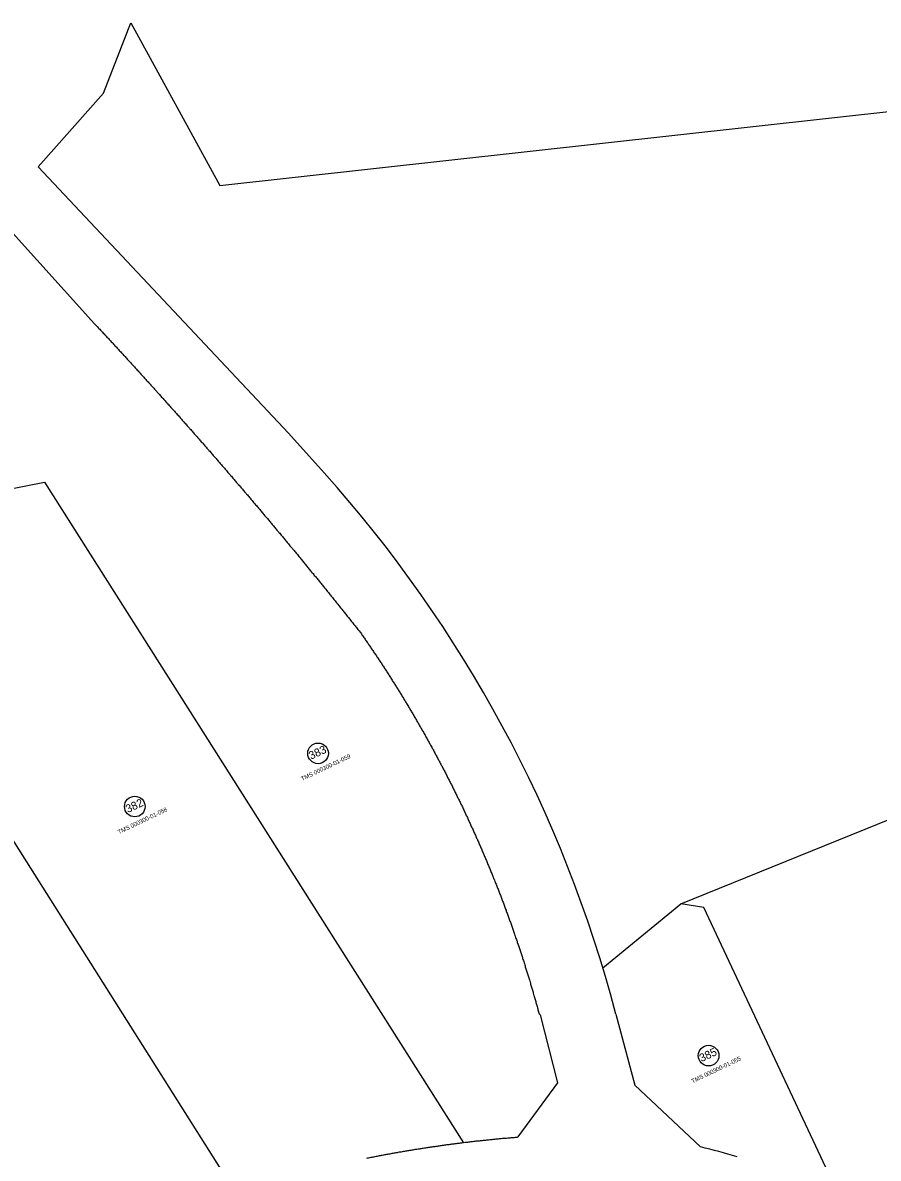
# Model space of a CAD drawing. Extents: x 1854757 to 1948870, y 823643 to 877716.
# Drawn here: x 1903282 to 1904083, y 853837 to 854901 of the extents above; entities that cross this region are included whole.
import ezdxf

# ---------------------------------------------------------------- set-up
doc = ezdxf.new("R2010")
doc.units = 0
for name, color, linetype in [('Butler baseline', 7, 'Continuous'), ('Flatiron trailer_2', 7, 'Continuous'), ('RD_EX_H2O_WetLd', 7, 'Continuous'), ('RD_SMD_Misc', 7, 'Continuous')]:
    doc.layers.add(name, color=color, linetype=linetype)

msp = doc.modelspace()

# ---------------------------------------------------------------- linework, layer by layer
at = {"layer": 'Butler baseline'}
for centre in [(1903558.5, 854216.2), (1903386.8, 854166.4), (1903924.4, 853933)]:
    msp.add_circle(centre, 9.65, dxfattribs=at)
at = {"layer": 'RD_EX_H2O_WetLd'}
for p, q in [((1903357.4, 854834.7), (1903383.1, 854900.8)), ((1903383.1, 854900.8), (1903466.5, 854748.3)), ((1903466.5, 854748.3), (1904319.8, 854842.7)), ((1903296.4, 854765.7), (1903357.4, 854834.7)), ((1903530.7, 854516.1), (1903296.4, 854765.7)), ((1903898.5, 854075.1), (1904882, 854475.2)), ((1903825.3, 854015.4), (1903898.5, 854075.1)), ((1903919.8, 854071.8), (1903898.5, 854075.1)), ((1904046.6, 853801.8), (1903919.8, 854071.8))]:
    msp.add_line(p, q, dxfattribs=at)
for points in [[(1903266.6, 854710.2), (1903349.1, 854618.7), (1903349.8, 854618), (1903350.5, 854617.2), (1903351.2, 854616.5), (1903351.9, 854615.8), (1903352.5, 854615), (1903353.2, 854614.3), (1903353.9, 854613.6), (1903354.6, 854612.8), (1903355.3, 854612.1), (1903356, 854611.4), (1903356.6, 854610.7), (1903357.3, 854609.9), (1903358, 854609.2), (1903358.7, 854608.5), (1903359.4, 854607.7), (1903360, 854607), (1903360.7, 854606.3), (1903361.4, 854605.5), (1903362.1, 854604.8), (1903362.8, 854604.1), (1903363.4, 854603.3), (1903364.1, 854602.6), (1903364.8, 854601.9), (1903365.5, 854601.1), (1903366.2, 854600.4), (1903366.8, 854599.6), (1903367.5, 854598.9), (1903368.2, 854598.2), (1903368.9, 854597.4), (1903369.5, 854596.7), (1903370.2, 854596), (1903370.9, 854595.2), (1903371.6, 854594.5), (1903372.3, 854593.8), (1903372.9, 854593), (1903373.6, 854592.3), (1903374.3, 854591.6), (1903375, 854590.8), (1903375.6, 854590.1), (1903376.3, 854589.3), (1903377, 854588.6), (1903377.7, 854587.9), (1903378.3, 854587.1), (1903379, 854586.4), (1903379.7, 854585.7), (1903380.4, 854584.9), (1903381, 854584.2), (1903381.7, 854583.5), (1903382.4, 854582.7), (1903383.1, 854582), (1903383.7, 854581.2), (1903384.4, 854580.5), (1903385.1, 854579.8), (1903385.8, 854579), (1903386.4, 854578.3), (1903387.1, 854577.5), (1903387.8, 854576.8), (1903388.5, 854576.1), (1903389.1, 854575.3), (1903389.8, 854574.6), (1903390.5, 854573.8), (1903391.2, 854573.1), (1903391.8, 854572.4), (1903392.5, 854571.6), (1903393.2, 854570.9), (1903393.8, 854570.1), (1903394.5, 854569.4), (1903395.2, 854568.7), (1903395.9, 854567.9), (1903396.5, 854567.2), (1903397.2, 854566.4), (1903397.9, 854565.7), (1903398.5, 854565), (1903399.2, 854564.2), (1903399.9, 854563.5), (1903400.6, 854562.7), (1903401.2, 854562), (1903401.9, 854561.3), (1903402.6, 854560.5), (1903403.2, 854559.8), (1903403.9, 854559), (1903404.6, 854558.3), (1903405.3, 854557.5), (1903405.9, 854556.8), (1903406.6, 854556.1), (1903407.3, 854555.3), (1903407.9, 854554.6), (1903408.6, 854553.8), (1903409.3, 854553.1), (1903409.9, 854552.3), (1903410.6, 854551.6), (1903411.3, 854550.9), (1903411.9, 854550.1), (1903412.6, 854549.4), (1903413.3, 854548.6), (1903413.9, 854547.9), (1903414.6, 854547.1), (1903415.3, 854546.4), (1903415.9, 854545.6), (1903416.6, 854544.9), (1903417.3, 854544.2), (1903417.9, 854543.4), (1903418.6, 854542.7), (1903419.3, 854541.9), (1903419.9, 854541.2), (1903420.6, 854540.4), (1903421.3, 854539.7), (1903421.9, 854538.9), (1903422.6, 854538.2), (1903423.3, 854537.4), (1903423.9, 854536.7), (1903424.6, 854535.9), (1903425.3, 854535.2), (1903425.9, 854534.5), (1903426.6, 854533.7), (1903427.3, 854533), (1903427.9, 854532.2), (1903428.6, 854531.5), (1903429.3, 854530.7), (1903429.9, 854530), (1903430.6, 854529.2), (1903431.2, 854528.5), (1903431.9, 854527.7), (1903432.6, 854527), (1903433.2, 854526.2), (1903433.9, 854525.5), (1903434.6, 854524.7), (1903435.2, 854524), (1903435.9, 854523.2), (1903436.5, 854522.5), (1903437.2, 854521.7), (1903437.9, 854521), (1903438.5, 854520.2), (1903439.2, 854519.5), (1903439.9, 854518.7), (1903440.5, 854518), (1903441.2, 854517.2), (1903441.8, 854516.5), (1903442.5, 854515.7), (1903443.2, 854515), (1903443.8, 854514.2), (1903444.5, 854513.5), (1903445.1, 854512.7), (1903445.8, 854512), (1903446.5, 854511.2), (1903447.1, 854510.5), (1903447.8, 854509.7), (1903448.4, 854509), (1903449.1, 854508.2), (1903449.8, 854507.5), (1903450.4, 854506.7), (1903451.1, 854506), (1903451.7, 854505.2), (1903452.4, 854504.5), (1903453.1, 854503.7), (1903453.7, 854503), (1903454.4, 854502.2), (1903455, 854501.4), (1903455.7, 854500.7), (1903456.3, 854499.9), (1903457, 854499.2), (1903457.7, 854498.4), (1903458.3, 854497.7), (1903459, 854496.9), (1903459.6, 854496.2), (1903460.3, 854495.4), (1903460.9, 854494.7), (1903461.6, 854493.9), (1903462.3, 854493.1), (1903462.9, 854492.4), (1903463.6, 854491.6), (1903464.2, 854490.9), (1903464.9, 854490.1), (1903465.5, 854489.4), (1903466.2, 854488.6), (1903466.8, 854487.9), (1903467.5, 854487.1), (1903468.1, 854486.4), (1903468.8, 854485.6), (1903469.5, 854484.8), (1903470.1, 854484.1), (1903470.8, 854483.3), (1903471.4, 854482.6), (1903472.1, 854481.8), (1903472.7, 854481.1), (1903473.4, 854480.3), (1903474, 854479.5), (1903474.7, 854478.8), (1903475.3, 854478), (1903476, 854477.3), (1903476.6, 854476.5), (1903477.3, 854475.8), (1903478, 854475), (1903478.6, 854474.2), (1903479.3, 854473.5), (1903479.9, 854472.7), (1903480.6, 854472), (1903481.2, 854471.2), (1903481.9, 854470.4), (1903482.5, 854469.7), (1903483.2, 854468.9), (1903483.8, 854468.2), (1903484.5, 854467.4), (1903485.1, 854466.6), (1903485.8, 854465.9), (1903486.4, 854465.1), (1903487.1, 854464.4), (1903487.7, 854463.6), (1903488.4, 854462.8), (1903489, 854462.1), (1903489.7, 854461.3), (1903490.3, 854460.6), (1903491, 854459.8), (1903491.6, 854459), (1903492.3, 854458.3), (1903492.9, 854457.5), (1903493.6, 854456.8), (1903494.2, 854456), (1903494.9, 854455.2), (1903495.5, 854454.5), (1903496.1, 854453.7), (1903496.8, 854453), (1903497.4, 854452.2), (1903498.1, 854451.4), (1903498.7, 854450.7), (1903499.4, 854449.9), (1903500, 854449.1), (1903500.7, 854448.4), (1903501.3, 854447.6), (1903502, 854446.9), (1903502.6, 854446.1), (1903503.3, 854445.3), (1903503.9, 854444.6), (1903504.6, 854443.8), (1903505.2, 854443), (1903505.8, 854442.3), (1903506.5, 854441.5), (1903507.1, 854440.7), (1903507.8, 854440), (1903508.4, 854439.2), (1903509.1, 854438.4), (1903509.7, 854437.7), (1903510.4, 854436.9), (1903511, 854436.2), (1903511.6, 854435.4), (1903512.3, 854434.6), (1903512.9, 854433.9), (1903513.6, 854433.1), (1903514.2, 854432.3), (1903514.9, 854431.6), (1903515.5, 854430.8), (1903516.1, 854430), (1903516.8, 854429.3), (1903517.4, 854428.5), (1903518.1, 854427.7), (1903518.7, 854427), (1903519.4, 854426.2), (1903520, 854425.4), (1903520.6, 854424.7), (1903521.3, 854423.9), (1903521.9, 854423.1), (1903522.6, 854422.4), (1903523.2, 854421.6), (1903523.8, 854420.8), (1903524.5, 854420.1), (1903525.1, 854419.3), (1903525.8, 854418.5), (1903526.4, 854417.8), (1903527, 854417), (1903527.7, 854416.2), (1903528.3, 854415.4), (1903529, 854414.7), (1903529.6, 854413.9), (1903530.2, 854413.1), (1903530.9, 854412.4), (1903531.5, 854411.6), (1903532.2, 854410.8), (1903532.8, 854410.1), (1903533.4, 854409.3), (1903534.1, 854408.5), (1903534.7, 854407.8), (1903535.4, 854407), (1903536, 854406.2), (1903536.6, 854405.4), (1903537.3, 854404.7), (1903537.9, 854403.9), (1903538.5, 854403.1), (1903539.2, 854402.4), (1903539.8, 854401.6), (1903540.5, 854400.8), (1903541.1, 854400), (1903541.7, 854399.3), (1903542.4, 854398.5), (1903543, 854397.7), (1903543.6, 854397), (1903544.3, 854396.2), (1903544.9, 854395.4), (1903545.5, 854394.6), (1903546.2, 854393.9), (1903546.8, 854393.1), (1903547.4, 854392.3), (1903548.1, 854391.6), (1903548.7, 854390.8), (1903549.3, 854390), (1903550, 854389.2), (1903550.6, 854388.5), (1903551.2, 854387.7), (1903551.9, 854386.9), (1903552.5, 854386.1), (1903553.1, 854385.4), (1903553.8, 854384.6), (1903554.4, 854383.8), (1903555, 854383), (1903555.7, 854382.3), (1903556.3, 854381.5), (1903556.9, 854380.7), (1903557.6, 854379.9), (1903558.2, 854379.2), (1903558.8, 854378.4), (1903559.5, 854377.6), (1903560.1, 854376.8), (1903560.7, 854376.1), (1903561.4, 854375.3), (1903562, 854374.5), (1903562.6, 854373.7), (1903563.3, 854373), (1903563.9, 854372.2), (1903564.5, 854371.4), (1903565.1, 854370.6), (1903565.8, 854369.9), (1903566.4, 854369.1), (1903567, 854368.3), (1903567.7, 854367.5), (1903568.3, 854366.8), (1903568.9, 854366), (1903569.6, 854365.2), (1903570.2, 854364.4), (1903570.8, 854363.6), (1903571.4, 854362.9), (1903572.1, 854362.1), (1903572.7, 854361.3), (1903573.3, 854360.5), (1903574, 854359.8), (1903574.6, 854359), (1903575.2, 854358.2), (1903575.8, 854357.4), (1903576.5, 854356.6), (1903577.1, 854355.9), (1903577.7, 854355.1), (1903578.3, 854354.3), (1903579, 854353.5), (1903579.6, 854352.7), (1903580.2, 854352), (1903580.9, 854351.2), (1903581.5, 854350.4), (1903582.1, 854349.6), (1903582.7, 854348.8), (1903583.4, 854348.1), (1903584, 854347.3), (1903584.6, 854346.5), (1903585.2, 854345.7), (1903585.9, 854344.9), (1903586.5, 854344.2), (1903587.1, 854343.4), (1903587.7, 854342.6), (1903588.4, 854341.8), (1903589, 854341), (1903589.6, 854340.2), (1903590.2, 854339.5), (1903590.8, 854338.7), (1903591.5, 854337.9), (1903592.1, 854337.1), (1903592.7, 854336.3), (1903593.3, 854335.6), (1903594, 854334.8), (1903594.6, 854334), (1903595.2, 854333.2), (1903595.8, 854332.4), (1903596.4, 854331.6), (1903597.1, 854330.9), (1903597.9, 854329.8), (1903598.5, 854329), (1903599.1, 854328.2), (1903599.6, 854327.3), (1903600.2, 854326.5), (1903600.8, 854325.7), (1903601.3, 854324.9), (1903601.9, 854324.1), (1903602.5, 854323.2), (1903603.1, 854322.4), (1903603.6, 854321.6), (1903604.2, 854320.8), (1903604.8, 854319.9), (1903605.3, 854319.1), (1903605.9, 854318.3), (1903606.4, 854317.5), (1903607, 854316.6), (1903607.6, 854315.8), (1903608.1, 854315), (1903608.7, 854314.2), (1903609.3, 854313.3), (1903609.8, 854312.5), (1903610.4, 854311.7), (1903610.9, 854310.8), (1903611.5, 854310), (1903612.1, 854309.2), (1903612.6, 854308.4), (1903613.2, 854307.5), (1903613.7, 854306.7), (1903614.3, 854305.9), (1903614.8, 854305), (1903615.4, 854304.2), (1903615.9, 854303.4), (1903616.5, 854302.5), (1903617, 854301.7), (1903617.6, 854300.9), (1903618.1, 854300), (1903618.7, 854299.2), (1903619.2, 854298.3), (1903619.8, 854297.5), (1903620.3, 854296.7), (1903620.9, 854295.8), (1903621.4, 854295), (1903621.9, 854294.1), (1903622.5, 854293.3), (1903623, 854292.5), (1903623.6, 854291.6), (1903624.1, 854290.8), (1903624.7, 854289.9), (1903625.2, 854289.1), (1903625.7, 854288.3), (1903626.3, 854287.4), (1903626.8, 854286.6), (1903627.3, 854285.7), (1903627.9, 854284.9), (1903628.4, 854284), (1903629, 854283.2), (1903629.5, 854282.4), (1903630, 854281.5), (1903630.5, 854280.7), (1903631.1, 854279.8), (1903631.6, 854279), (1903632.1, 854278.1), (1903632.7, 854277.3), (1903633.2, 854276.4), (1903633.7, 854275.6), (1903634.3, 854274.7), (1903634.8, 854273.9), (1903635.3, 854273), (1903635.8, 854272.2), (1903636.3, 854271.3), (1903636.9, 854270.5), (1903637.4, 854269.6), (1903637.9, 854268.8), (1903638.4, 854267.9), (1903639, 854267), (1903639.5, 854266.2), (1903640, 854265.3), (1903640.5, 854264.5), (1903641, 854263.6), (1903641.5, 854262.8), (1903642.1, 854261.9), (1903642.6, 854261.1), (1903643.1, 854260.2), (1903643.6, 854259.3), (1903644.1, 854258.5), (1903644.6, 854257.6), (1903645.1, 854256.8), (1903645.6, 854255.9), (1903646.2, 854255), (1903646.7, 854254.2), (1903647.2, 854253.3), (1903647.7, 854252.5), (1903648.2, 854251.6), (1903648.7, 854250.7), (1903649.2, 854249.9), (1903649.7, 854249), (1903650.2, 854248.1), (1903650.7, 854247.3), (1903651.2, 854246.4), (1903651.7, 854245.5), (1903652.2, 854244.7), (1903652.7, 854243.8), (1903653.2, 854242.9), (1903653.7, 854242.1), (1903654.2, 854241.2), (1903654.7, 854240.3), (1903655.2, 854239.5), (1903655.7, 854238.6), (1903656.2, 854237.7), (1903656.7, 854236.9), (1903657.2, 854236), (1903657.7, 854235.1), (1903658.2, 854234.3), (1903658.7, 854233.4), (1903659.1, 854232.5), (1903659.6, 854231.6), (1903660.1, 854230.8), (1903660.6, 854229.9), (1903661.1, 854229), (1903661.6, 854228.1), (1903662.1, 854227.3), (1903662.5, 854226.4), (1903663, 854225.5), (1903663.5, 854224.7), (1903664, 854223.8), (1903664.5, 854222.9), (1903665, 854222), (1903665.4, 854221.1), (1903665.9, 854220.3), (1903666.4, 854219.4), (1903666.9, 854218.5), (1903667.4, 854217.6), (1903667.8, 854216.7), (1903668.3, 854215.9), (1903668.8, 854215), (1903669.3, 854214.1), (1903669.7, 854213.2), (1903670.2, 854212.3), (1903670.7, 854211.5), (1903671.1, 854210.6), (1903671.6, 854209.7), (1903672.1, 854208.8), (1903672.5, 854207.9), (1903673, 854207), (1903673.5, 854206.2), (1903673.9, 854205.3), (1903674.4, 854204.4), (1903674.9, 854203.5), (1903675.3, 854202.6), (1903675.8, 854201.7), (1903676.3, 854200.8), (1903676.7, 854200), (1903677.2, 854199.1), (1903677.6, 854198.2), (1903678.1, 854197.3), (1903678.6, 854196.4), (1903679, 854195.5), (1903679.5, 854194.6), (1903679.9, 854193.7), (1903680.4, 854192.8), (1903680.8, 854192), (1903681.3, 854191.1), (1903681.8, 854190.2), (1903682.2, 854189.3), (1903682.7, 854188.4), (1903683.1, 854187.5), (1903683.6, 854186.6), (1903684, 854185.7), (1903684.5, 854184.8), (1903684.9, 854183.9), (1903685.3, 854183), (1903685.8, 854182.1), (1903686.2, 854181.2), (1903686.7, 854180.3), (1903687.1, 854179.4), (1903687.6, 854178.5), (1903688, 854177.7), (1903688.5, 854176.8), (1903688.9, 854175.9), (1903689.3, 854175), (1903689.8, 854174.1), (1903690.2, 854173.2), (1903690.6, 854172.3), (1903691.1, 854171.4), (1903691.5, 854170.5), (1903691.9, 854169.6), (1903692.4, 854168.7), (1903692.8, 854167.8), (1903693.2, 854166.9), (1903693.7, 854166), (1903694.1, 854165.1), (1903694.5, 854164.2), (1903695, 854163.2), (1903695.4, 854162.3), (1903695.8, 854161.4), (1903696.3, 854160.5), (1903696.7, 854159.6), (1903697.1, 854158.7), (1903697.5, 854157.8), (1903698, 854156.9), (1903698.4, 854156), (1903698.8, 854155.1), (1903699.2, 854154.2), (1903699.6, 854153.3), (1903700.1, 854152.4), (1903700.5, 854151.5), (1903700.9, 854150.6), (1903701.3, 854149.7), (1903701.7, 854148.7), (1903702.1, 854147.8), (1903702.6, 854146.9), (1903703, 854146), (1903703.4, 854145.1), (1903703.8, 854144.2), (1903704.2, 854143.3), (1903704.6, 854142.4), (1903705, 854141.5), (1903705.4, 854140.5), (1903705.9, 854139.6), (1903706.3, 854138.7), (1903706.7, 854137.8), (1903707.1, 854136.9), (1903707.5, 854136), (1903707.9, 854135.1), (1903708.3, 854134.2), (1903708.7, 854133.2), (1903709.1, 854132.3), (1903709.5, 854131.4), (1903709.9, 854130.5), (1903710.3, 854129.6), (1903710.7, 854128.7), (1903711.1, 854127.7), (1903711.5, 854126.8), (1903711.9, 854125.9), (1903712.3, 854125), (1903712.7, 854124.1), (1903713.1, 854123.1), (1903713.5, 854122.2), (1903713.9, 854121.3), (1903714.2, 854120.4), (1903714.6, 854119.5), (1903715, 854118.5), (1903715.4, 854117.6), (1903715.8, 854116.7), (1903716.2, 854115.8), (1903716.6, 854114.9), (1903717, 854113.9), (1903717.4, 854113), (1903717.7, 854112.1), (1903718.1, 854111.2), (1903718.5, 854110.2), (1903718.9, 854109.3), (1903719.3, 854108.4), (1903719.7, 854107.5), (1903720, 854106.5), (1903720.4, 854105.6), (1903720.8, 854104.7), (1903721.2, 854103.8), (1903721.5, 854102.8), (1903721.9, 854101.9), (1903722.3, 854101), (1903722.7, 854100.1), (1903723, 854099.1), (1903723.4, 854098.2), (1903723.8, 854097.3), (1903724.2, 854096.3), (1903724.5, 854095.4), (1903724.9, 854094.5), (1903725.3, 854093.6), (1903725.6, 854092.6), (1903726, 854091.7), (1903726.4, 854090.8), (1903726.7, 854089.8), (1903727.1, 854088.9), (1903727.5, 854088), (1903727.8, 854087), (1903728.2, 854086.1), (1903728.5, 854085.2), (1903728.9, 854084.2), (1903729.3, 854083.3), (1903729.6, 854082.4), (1903730, 854081.4), (1903730.3, 854080.5), (1903730.7, 854079.6), (1903731, 854078.6), (1903731.4, 854077.7), (1903731.8, 854076.8), (1903732.1, 854075.8), (1903732.5, 854074.9), (1903732.8, 854074), (1903733.2, 854073), (1903733.5, 854072.1), (1903733.9, 854071.1), (1903734.2, 854070.2), (1903734.6, 854069.3), (1903734.9, 854068.3), (1903735.2, 854067.4), (1903735.6, 854066.5), (1903735.9, 854065.5), (1903736.3, 854064.6), (1903736.6, 854063.6), (1903737, 854062.7), (1903737.3, 854061.8), (1903737.6, 854060.8), (1903738, 854059.9), (1903738.3, 854058.9), (1903738.7, 854058), (1903739, 854057.1), (1903739.3, 854056.1), (1903739.7, 854055.2), (1903740, 854054.2), (1903740.3, 854053.3), (1903740.7, 854052.3), (1903741, 854051.4), (1903741.3, 854050.5), (1903741.6, 854049.5), (1903742, 854048.6), (1903742.3, 854047.6), (1903742.6, 854046.7), (1903743, 854045.7), (1903743.3, 854044.8), (1903743.6, 854043.8), (1903743.9, 854042.9), (1903744.3, 854041.9), (1903744.6, 854041), (1903744.9, 854040.1), (1903745.2, 854039.1), (1903745.5, 854038.2), (1903745.9, 854037.2), (1903746.2, 854036.3), (1903746.5, 854035.3), (1903746.8, 854034.4), (1903747.1, 854033.4), (1903747.4, 854032.5), (1903747.8, 854031.5), (1903748.1, 854030.6), (1903748.4, 854029.6), (1903748.7, 854028.7), (1903749, 854027.7), (1903749.3, 854026.8), (1903749.6, 854025.8), (1903749.9, 854024.9), (1903750.2, 854023.9), (1903750.5, 854023), (1903750.9, 854022), (1903751.2, 854021.1), (1903751.5, 854020.1), (1903751.8, 854019.2), (1903752.1, 854018.2), (1903752.4, 854017.2), (1903752.7, 854016.3), (1903753, 854015.3), (1903753.3, 854014.4), (1903753.6, 854013.4), (1903753.9, 854012.5), (1903754.2, 854011.5), (1903754.5, 854010.6), (1903754.8, 854009.6), (1903755, 854008.7), (1903755.3, 854007.7), (1903755.6, 854006.7), (1903755.9, 854005.8), (1903756.2, 854004.8), (1903756.5, 854003.9), (1903756.8, 854002.9), (1903757.1, 854002), (1903757.4, 854001), (1903757.7, 854000), (1903757.9, 853999.1), (1903758.2, 853998.1), (1903758.5, 853997.2), (1903758.8, 853996.2), (1903759.1, 853995.2), (1903759.4, 853994.3), (1903759.6, 853993.3), (1903759.9, 853992.4), (1903760.2, 853991.4), (1903760.5, 853990.4), (1903760.8, 853989.5), (1903761, 853988.5), (1903761.3, 853987.6), (1903761.6, 853986.6), (1903761.9, 853985.6), (1903762.1, 853984.7), (1903762.4, 853983.7), (1903762.7, 853982.8), (1903762.9, 853981.8), (1903763.2, 853980.8), (1903763.5, 853979.9), (1903763.7, 853978.9), (1903764, 853977.9), (1903764.3, 853977), (1903764.5, 853976), (1903764.8, 853975), (1903765.1, 853974.1), (1903765.3, 853973.1), (1903765.6, 853972.2), (1903766.6, 853971.3), (1903783, 853907.5), (1903745.6, 853856.9), (1903745.2, 853856.3), (1903744.2, 853856.3), (1903743.2, 853856.2), (1903742.2, 853856.1), (1903741.2, 853856), (1903740.2, 853855.9), (1903739.2, 853855.9), (1903738.2, 853855.8), (1903737.2, 853855.7), (1903736.2, 853855.6), (1903735.2, 853855.5), (1903734.2, 853855.4), (1903733.2, 853855.4), (1903732.2, 853855.3), (1903731.2, 853855.2), (1903730.2, 853855.1), (1903729.2, 853855), (1903728.2, 853854.9), (1903727.2, 853854.8), (1903726.2, 853854.7), (1903725.2, 853854.6), (1903724.2, 853854.5), (1903723.2, 853854.4), (1903722.2, 853854.3), (1903721.2, 853854.2), (1903720.3, 853854.1), (1903719.3, 853854), (1903718.3, 853853.9), (1903717.3, 853853.8), (1903716.3, 853853.7), (1903715.3, 853853.6), (1903714.3, 853853.5), (1903713.3, 853853.4), (1903712.3, 853853.3), (1903711.3, 853853.2), (1903710.3, 853853.1), (1903709.3, 853853), (1903708.3, 853852.9), (1903707.3, 853852.8), (1903706.3, 853852.7), (1903705.3, 853852.6), (1903704.3, 853852.4), (1903703.3, 853852.3), (1903702.4, 853852.2), (1903701.4, 853852.1), (1903700.4, 853852), (1903699.4, 853851.9), (1903698.4, 853851.7), (1903697.4, 853851.6), (1903696.4, 853851.5), (1903694.8, 853851.3)], [(1903494.1, 853784.8), (1902909.8, 854708.8)], [(1903171.5, 854444.6), (1903302.2, 854470.2), (1903694.8, 853851.3), (1903693.8, 853851.2), (1903692.8, 853851.1), (1903691.8, 853850.9), (1903690.8, 853850.8), (1903689.8, 853850.7), (1903688.8, 853850.6), (1903687.8, 853850.4), (1903686.8, 853850.3), (1903685.8, 853850.2), (1903684.8, 853850.1), (1903683.8, 853849.9), (1903682.9, 853849.8), (1903681.9, 853849.7), (1903680.9, 853849.5), (1903679.9, 853849.4), (1903678.9, 853849.3), (1903677.9, 853849.1), (1903676.9, 853849), (1903675.9, 853848.9), (1903674.9, 853848.7), (1903673.9, 853848.6), (1903672.9, 853848.5), (1903672, 853848.3), (1903671, 853848.2), (1903670, 853848), (1903669, 853847.9), (1903668, 853847.7), (1903667, 853847.6), (1903666, 853847.5), (1903665, 853847.3), (1903664, 853847.2), (1903663.1, 853847), (1903662.1, 853846.9), (1903661.1, 853846.7), (1903660.1, 853846.6), (1903659.1, 853846.4), (1903658.1, 853846.3), (1903657.1, 853846.1), (1903656.1, 853846), (1903655.1, 853845.8), (1903654.2, 853845.7), (1903653.2, 853845.5), (1903652.2, 853845.3), (1903651.2, 853845.2), (1903650.2, 853845), (1903649.2, 853844.9), (1903648.2, 853844.7), (1903647.2, 853844.5), (1903646.3, 853844.4), (1903645.3, 853844.2), (1903644.3, 853844.1), (1903643.3, 853843.9), (1903642.3, 853843.7), (1903641.3, 853843.6), (1903640.3, 853843.4), (1903639.4, 853843.2), (1903638.4, 853843.1), (1903637.4, 853842.9), (1903636.4, 853842.7), (1903635.4, 853842.6), (1903634.4, 853842.4), (1903633.4, 853842.2), (1903632.5, 853842), (1903631.5, 853841.9), (1903630.5, 853841.7), (1903629.5, 853841.5), (1903628.5, 853841.3), (1903627.5, 853841.2), (1903626.6, 853841), (1903625.6, 853840.8), (1903624.6, 853840.6), (1903623.6, 853840.4), (1903622.6, 853840.3), (1903621.6, 853840.1), (1903620.7, 853839.9), (1903619.7, 853839.7), (1903618.7, 853839.5), (1903617.7, 853839.3), (1903616.7, 853839.2), (1903615.7, 853839), (1903614.8, 853838.8), (1903613.8, 853838.6), (1903612.8, 853838.4), (1903611.8, 853838.2), (1903610.8, 853838), (1903609.8, 853837.8), (1903608.9, 853837.6), (1903607.9, 853837.4), (1903606.9, 853837.2), (1903605.9, 853837), (1903604.9, 853836.9), (1903604, 853836.7)]]:
    msp.add_lwpolyline(points, dxfattribs=at)
at = {"layer": 'RD_SMD_Misc'}
for p, q in [((1903530.7, 854516.1), (1903564.2, 854478.9)), ((1903837.6, 853972), (1903855.2, 853905.3)), ((1903855.2, 853905.3), (1903916.9, 853847.4))]:
    msp.add_line(p, q, dxfattribs=at)
for centre, radius, start, end in [((1902652.9, 853660.1), 1225.1, 14.7485, 41.9401), ((1903780, 853276.2), 587.4, 73.0696, 76.5195)]:
    msp.add_arc(centre, radius, start, end, dxfattribs=at)

# ---------------------------------------------------------------- texts
at = {"layer": 'Butler baseline'}
for s, p in [('383', (1903551.9, 854210.2)), ('382', (1903380.3, 854160.3)), ('385', (1903917.8, 853926.9))]:
    msp.add_text(s, height=7.5, rotation=24.8809, dxfattribs=at).set_placement(p)
at = {"layer": 'Flatiron trailer_2'}
for s, p in [('TMS 000300-01-059', (1903543.7, 854190.3)), ('TMS 000300-01-058', (1903372, 854140.4)), ('TMS 000300-01-055', (1903909.5, 853907))]:
    msp.add_text(s, height=4, rotation=25.6077, dxfattribs=at).set_placement(p)

doc.saveas('drawing.dxf')
